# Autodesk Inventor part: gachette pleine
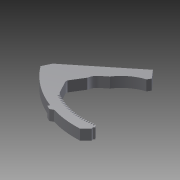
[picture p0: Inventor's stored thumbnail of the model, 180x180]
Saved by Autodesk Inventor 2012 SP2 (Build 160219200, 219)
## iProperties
Created: 2013-11
Part Number: gachette pleine
Material: Default
Document SubType Name: Modeling
Designer: Administrateur
Density: 1 g/cm^3
Norme de conversion: STEP AP214IS
Nom du fichier: D:\dominique\travail\annÃ©e 2013-2014\TSTI2D\ITEC\activitÃ© 5 moulage sous vide\tracÃ© gachette.stp
Préprocesseur: Autodesk Inventor 2014
Postprocesseur: Build: 219, Release: 2012 SP2 - Date: Fri 04/27/2012
Unités envoyées: centimètre
Incertitude: 0.001
Author: Administrateur
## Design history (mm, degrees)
node "Pièce11"
  sketch "Esquisse 3D1"
sketch "Esquisse1"
  geometry: L1 (515.638, -308.172)-(533.864, -293.457) reference; L2 (596.473, -245.495)-(602.628, -235.545) reference; L3 (602.628, -235.545)-(581.113, -210.555) reference; L4 (581.113, -210.555)-(412.938, -346.327) reference; L5 (412.938, -346.327)-(401.039, -371.433) reference; L6 (517.935, -459.234)-(515.638, -465.322) reference; L7 (515.638, -465.322)-(526.829, -470.626) reference; L8 (642.994, -458.727)-(625.373, -475.638) reference; L9 (480.211, -375.633)-(499.977, -412.731) reference; L10 (502.605, -330.527)-(480.211, -366.73) reference; L11 (636.939, -439.777)-(645.013, -449.154) reference; L12 (645.013, -449.154)-(640.976, -452.63) reference; L13 (640.976, -452.63)-(642.994, -458.727) reference; L14 (526.829, -470.626)-(536.52, -465.463) reference; A1 r 36.362 centre (538.479, -336.465) between (515.638, -308.172) and (502.605, -330.527) reference; A2 r 118.956 centre (633.418, -358.568) between (596.473, -245.495) and (533.864, -293.457) reference; A3 r 261.469 centre (610.255, -214.606) between (401.039, -371.433) and (517.935, -459.234) reference; A4 r 189.69 centre (602.628, -253.216) between (499.977, -412.731) and (636.939, -439.777) reference; A5 r 261.469 centre (610.255, -214.606) between (536.52, -465.463) and (625.373, -475.638) reference; A6 r 8.462 centre (487.408, -371.181) between (480.211, -366.73) and (480.211, -375.633); 1 further point
  constraints: 2 point on circle, 1 centre point, 1 tangent
  dimensions: "d5" = 189.68989 radius of A4 (derived)
extrude "Extrusion1" new body sketch "Esquisse1" distance "d0" = 31.5; taper "d1" = 0 deg
sketch "Esquisse3"
  geometry: L1 (642.994, -458.727)-(625.373, -475.638) reference; L2 (636.939, -439.777)-(645.013, -449.154) reference; L3 (480.211, -375.633)-(499.977, -412.731) reference; L4 (503.647, -415.033)-(498.767, -419.717); L5 (505.204, -415.976)-(503.32, -422.472); L6 (509.08, -418.234)-(504.358, -423.077); L7 (510.668, -419.124)-(509, -425.679); L8 (514.617, -421.252)-(510.058, -426.249); L9 (516.233, -422.089)-(514.785, -428.696); L10 (520.25, -424.085)-(515.861, -429.231); L11 (521.894, -424.867)-(520.666, -431.519); L12 (525.975, -426.728)-(521.759, -432.017); L13 (527.644, -427.456)-(526.638, -434.145); L14 (531.785, -429.18)-(527.747, -434.607); L15 (533.477, -429.852)-(532.693, -436.57); L16 (537.673, -431.438)-(533.817, -436.995); L17 (539.386, -432.053)-(538.826, -438.794); L18 (543.633, -433.498)-(539.964, -439.181); L19 (545.366, -434.056)-(545.03, -440.812); L20 (549.657, -435.359)-(546.18, -441.161); L21 (551.408, -435.859)-(551.297, -442.623); L22 (555.741, -437.019)-(552.458, -442.933); L23 (557.507, -437.461)-(557.621, -444.224); L24 (561.876, -438.476)-(558.791, -444.496); L25 (563.656, -438.859)-(563.995, -445.615); L26 (568.056, -439.729)-(565.174, -445.848); L27 (569.848, -440.052)-(570.411, -446.792); L28 (574.275, -440.775)-(571.597, -446.986); L29 (576.076, -441.038)-(576.863, -447.756); L30 (580.525, -441.613)-(578.055, -447.91); L31 (582.334, -441.817)-(583.343, -448.505); L32 (586.799, -442.244)-(584.54, -448.62); L33 (588.614, -442.387)-(589.845, -449.038); L34 (593.091, -442.666)-(591.044, -449.113); L35 (594.909, -442.748)-(596.361, -449.355); L36 (599.393, -442.878)-(597.562, -449.39); L37 (601.213, -442.9)-(602.884, -449.455); L38 (605.699, -442.881)-(604.085, -449.45); L39 (607.519, -442.843)-(609.406, -449.338); L40 (612.001, -442.674)-(610.607, -449.293); L41 (613.819, -442.575)-(615.921, -449.004); L42 (618.293, -442.258)-(617.12, -448.919); L43 (620.107, -442.099)-(622.422, -448.454); L44 (624.568, -441.633)-(623.617, -448.329); L45 (626.375, -441.413)-(628.9, -447.689); L46 (630.818, -440.799)-(630.09, -447.524); L47 (632.618, -440.52)-(635.349, -446.708); L48 (637.981, -440.987)-(637.4, -446.35); L49 (637.981, -440.987)-(636.939, -439.777); A1 r 189.69 centre (602.628, -253.216) between (499.977, -412.731) and (636.939, -439.777) reference; A2 r 196.239 centre (602.628, -253.216) between (503.32, -422.472) and (504.358, -423.077); A3 r 196.239 centre (602.628, -253.216) between (509, -425.679) and (510.058, -426.249); A4 r 196.239 centre (602.628, -253.216) between (514.785, -428.696) and (515.861, -429.231); A5 r 196.239 centre (602.628, -253.216) between (520.666, -431.519) and (521.759, -432.017); A6 r 196.239 centre (602.628, -253.216) between (526.638, -434.145) and (527.747, -434.607); A7 r 196.239 centre (602.628, -253.216) between (532.693, -436.57) and (533.817, -436.995); A8 r 196.239 centre (602.628, -253.216) between (538.826, -438.794) and (539.964, -439.181); A9 r 196.239 centre (602.628, -253.216) between (545.03, -440.812) and (546.18, -441.161); A10 r 196.239 centre (602.628, -253.216) between (551.297, -442.623) and (552.458, -442.933); A11 r 196.239 centre (602.628, -253.216) between (557.621, -444.224) and (558.791, -444.496); A12 r 196.239 centre (602.628, -253.216) between (563.995, -445.615) and (565.174, -445.848); A13 r 196.239 centre (602.628, -253.216) between (570.411, -446.792) and (571.597, -446.986); A14 r 196.239 centre (602.628, -253.216) between (576.863, -447.756) and (578.055, -447.91); A15 r 196.239 centre (602.628, -253.216) between (583.343, -448.505) and (584.54, -448.62); A16 r 196.239 centre (602.628, -253.216) between (589.845, -449.038) and (591.044, -449.113); A17 r 196.239 centre (602.628, -253.216) between (596.361, -449.355) and (597.562, -449.39); A18 r 196.239 centre (602.628, -253.216) between (602.884, -449.455) and (604.085, -449.45); A19 r 196.239 centre (602.628, -253.216) between (609.406, -449.338) and (610.607, -449.293); A20 r 196.239 centre (602.628, -253.216) between (615.921, -449.004) and (617.12, -448.919); A21 r 196.239 centre (602.628, -253.216) between (622.422, -448.454) and (623.617, -448.329); A22 r 196.239 centre (602.628, -253.216) between (628.9, -447.689) and (630.09, -447.524); A23 r 196.239 centre (602.628, -253.216) between (635.349, -446.708) and (637.4, -446.35); A24 r 189.69 centre (602.628, -253.216) between (505.204, -415.976) and (509.08, -418.234); A25 r 189.69 centre (602.628, -253.216) between (510.668, -419.124) and (514.617, -421.252); A26 r 189.69 centre (602.628, -253.216) between (516.233, -422.089) and (520.25, -424.085); A27 r 189.69 centre (602.628, -253.216) between (521.894, -424.867) and (525.975, -426.728); A28 r 189.69 centre (602.628, -253.216) between (527.644, -427.456) and (531.785, -429.18); A29 r 189.69 centre (602.628, -253.216) between (533.477, -429.852) and (537.673, -431.438); A30 r 189.69 centre (602.628, -253.216) between (539.386, -432.053) and (543.633, -433.498); A31 r 189.69 centre (602.628, -253.216) between (545.366, -434.056) and (549.657, -435.359); A32 r 189.69 centre (602.628, -253.216) between (551.408, -435.859) and (555.741, -437.019); A33 r 189.69 centre (602.628, -253.216) between (557.507, -437.461) and (561.876, -438.476); A34 r 189.69 centre (602.628, -253.216) between (563.656, -438.859) and (568.056, -439.729); A35 r 189.69 centre (602.628, -253.216) between (569.848, -440.052) and (574.275, -440.775); A36 r 189.69 centre (602.628, -253.216) between (576.076, -441.038) and (580.525, -441.613); A37 r 189.69 centre (602.628, -253.216) between (582.334, -441.817) and (586.799, -442.244); A38 r 189.69 centre (602.628, -253.216) between (588.614, -442.387) and (593.091, -442.666); A39 r 189.69 centre (602.628, -253.216) between (594.909, -442.748) and (599.393, -442.878); A40 r 189.69 centre (602.628, -253.216) between (601.213, -442.9) and (605.699, -442.881); A41 r 189.69 centre (602.628, -253.216) between (607.519, -442.843) and (612.001, -442.674); A42 r 189.69 centre (602.628, -253.216) between (613.819, -442.575) and (618.293, -442.258); A43 r 189.69 centre (602.628, -253.216) between (620.107, -442.099) and (624.568, -441.633); A44 r 189.69 centre (602.628, -253.216) between (626.375, -441.413) and (630.818, -440.799); A45 r 189.69 centre (602.628, -253.216) between (632.618, -440.52) and (636.939, -439.777); A46 r 189.69 centre (602.628, -253.216) between (499.977, -412.731) and (503.647, -415.033); 1 further point
  constraints: 92 end point, 91 point on circle, 45 centre point, 2 coincident, 2 parallel, 2 point on line, 1 collinear, 127 other
  dimensions: "d9" = 40 deg dimension on A1.centre L4.start L46.start
extrude "Extrusion3" cut sketch "Esquisse3" stored distance "d11" = 10; taper "d12" = 0 deg
node "Solide1"
